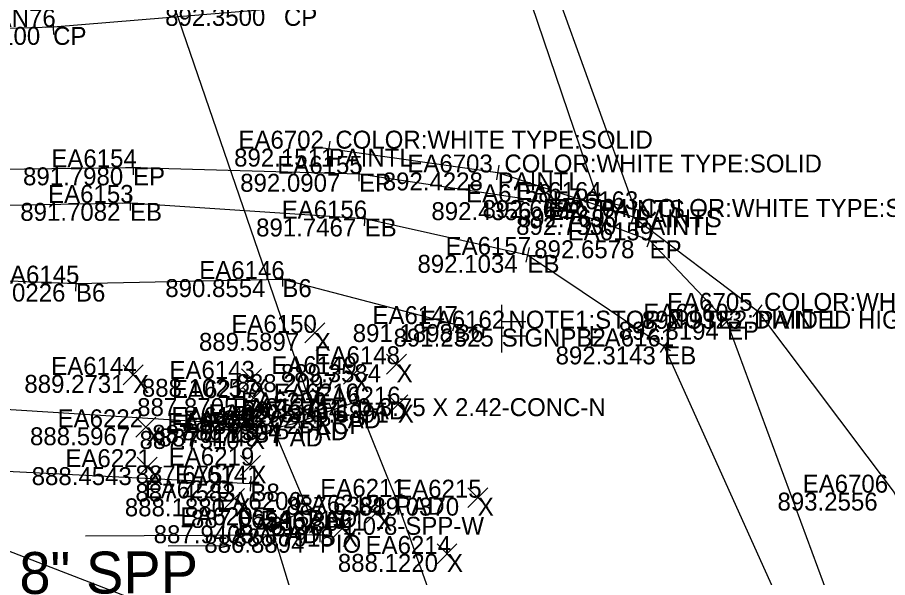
# Model space of a CAD drawing. Extents: x 179044 to 189691, y 286531 to 301257.
# Drawn here: x 180169.6 to 180227.8, y 300553.8 to 300591.3 of the extents above; entities that cross this region are included whole.
import ezdxf

# ---------------------------------------------------------------- set-up
doc = ezdxf.new("R2010")
doc.units = 0
for name, color, linetype in [('DR_X_Elev_Flow', 7, 'Continuous'), ('DR_X_Storm_Sewer', 7, 'Continuous'), ('DR_X_Text', 7, 'Continuous'), ('PM_X_Channelizing_Line', 7, 'Continuous'), ('PM_X_Stop_Line', 7, 'Continuous'), ('PV_X_COP', 7, 'Continuous'), ('PV_X_EOP', 7, 'Continuous'), ('PV_X_Shoulder_Aggregate', 7, 'Continuous'), ('RD_X_Concrete_Pad', 7, 'Continuous'), ('SN_X_Public', 7, 'Continuous'), ('SV_X_Break_Lines', 7, 'Continuous'), ('SV_X_Random_Point', 7, 'Continuous'), ('SV_X_Shot_Marker', 7, 'Continuous'), ('SV_X_Text_Comment', 7, 'Continuous'), ('SV_X_Text_Description', 7, 'Continuous'), ('SV_X_Text_Elevation', 7, 'Continuous'), ('SV_X_Text_Name', 7, 'Continuous')]:
    doc.layers.add(name, color=color, linetype=linetype)

msp = doc.modelspace()

# ---------------------------------------------------------------- linework, layer by layer
at = {"layer": 'DR_X_Elev_Flow'}
for p, q in [((180189.362, 300556.677), (180190.362, 300556.677)), ((180189.837, 300556.677), (180189.887, 300556.677)), ((180189.862, 300557.177), (180189.862, 300556.177)), ((180189.862, 300556.701), (180189.862, 300556.651)), ((180189.862, 300556.677), (180189.862, 300556.677)), ((180189.862, 300556.677), (180189.862, 300556.677))]:
    msp.add_line(p, q, dxfattribs=at)
at = {"layer": 'DR_X_Storm_Sewer'}
for p, q in [((180165.628, 300634.286), (180189.523, 300564.613)), ((180189.862, 300556.677), (180174.195, 300556.579))]:
    msp.add_line(p, q, dxfattribs=at)
at = {"layer": 'DR_X_Text'}
msp.add_line((180179.718, 300555.93), (180183.911, 300555.956), dxfattribs=at)
msp.add_lwpolyline([(180183.212, 300555.802), (180183.21, 300556.102), (180183.911, 300555.956)], close=True, dxfattribs=at)
at = {"layer": 'PM_X_Channelizing_Line'}
msp.add_lwpolyline([(180190.445, 300582.496), (180201.741, 300580.903), (180210.797, 300577.931), (180219.101, 300571.651), (180228.235, 300559.496), (180237.94, 300538.543), (180264.924, 300467.918), (180293.4, 300391.707), (180324.643, 300308.043), (180350.475, 300238.896)], dxfattribs=at)
at = {"layer": 'PM_X_Stop_Line'}
msp.add_lwpolyline([(180210.916, 300578.442), (180208.457, 300579.058), (180203.618, 300593.325), (180205.342, 300593.885)], close=True, dxfattribs=at)
at = {"layer": 'PV_X_COP'}
msp.add_lwpolyline([(179370.611, 300584.893), (179476.831, 300585.936), (179562.951, 300586.92), (179659.852, 300587.603), (179771.173, 300587.773), (179881.154, 300588.595), (179985.728, 300588.166), (180079.826, 300588.612), (180147.691, 300589.874), (180172.034, 300590.636), (180187.456, 300591.905), (180203.618, 300593.325)], dxfattribs=at)
at = {"layer": 'PV_X_EOP'}
msp.add_lwpolyline([(179371.146, 300578.051), (179477.168, 300579.528), (179563.012, 300579.455), (179660.626, 300579.907), (179772.349, 300580.843), (179883.302, 300581.216), (179986.953, 300581.659), (180080.461, 300581.624), (180131.142, 300581.875), (180152.421, 300580.897), (180177.372, 300581.245), (180192.481, 300580.813), (180205.116, 300578.916), (180211.895, 300576.366), (180217.061, 300570.924), (180226.256, 300546.032), (180252.64, 300475.662), (180284.891, 300388.784), (180312.046, 300315.753), (180341.998, 300235.308)], dxfattribs=at)
at = {"layer": 'PV_X_Shoulder_Aggregate'}
msp.add_lwpolyline([(179563.451, 300578.229), (179660.977, 300578.016), (179772.748, 300578.901), (179883.7, 300579.446), (179986.895, 300579.719), (180080.262, 300579.655), (180131.517, 300579.632), (180152.892, 300578.404), (180177.169, 300578.87), (180192.854, 300577.824), (180203.732, 300575.396), (180212.869, 300569.272), (180224.05, 300544.426), (180250.422, 300474.503), (180282.665, 300386.992), (180309.922, 300313.986), (180339.844, 300234.334)], dxfattribs=at)
at = {"layer": 'RD_X_Concrete_Pad'}
msp.add_lwpolyline([(180197.385, 300552.231), (180195.522, 300551.693), (180192.478, 300550.79), (180189.063, 300549.217), (180186.577, 300557.315), (180189.052, 300558.338), (180186.77, 300563.783), (180188.444, 300564.199), (180190.647, 300565), (180192.332, 300565.592), (180194.898, 300559.216)], close=True, dxfattribs=at)
at = {"layer": 'SN_X_Public'}
for p, q in [((180202.013, 300568.861), (180202.013, 300572.061)), ((180202.013, 300570.941), (180203.613, 300570.941)), ((180202.013, 300570.461), (180202.013, 300570.461)), ((180202.013, 300569.981), (180203.613, 300569.981))]:
    msp.add_line(p, q, dxfattribs=at)
at = {"layer": 'SV_X_Break_Lines'}
for points in [[(179565.115, 300573.15), (179662.025, 300574.398), (179773.068, 300575.457), (179882.867, 300576.482), (179986.954, 300576.827), (180079.906, 300577.073), (180132.276, 300575.162), (180173.558, 300573.472), (180187.352, 300573.774), (180198.853, 300570.766)], [(179565.766, 300571.109), (179663.199, 300570.888), (179773.087, 300572.831), (179882.326, 300573.106), (179987.447, 300574.391), (180079.006, 300574.101), (180132.144, 300569.99), (180164.614, 300565.351), (180185.409, 300564.026)], [(179565.763, 300567.872), (179663.335, 300568.017), (179772.883, 300569.466), (179881.609, 300569.697), (179987.857, 300571.139), (180079.155, 300570.638), (180132.418, 300565.887), (180165.824, 300561.088), (180185.221, 300560.101)], [(180320.902, 300212.184), (180282.069, 300307.438), (180254.033, 300376.286), (180214.216, 300457.225), (180192.833, 300518.475), (180187.002, 300524.649), (180178.544, 300551.918), (180167.492, 300556.189), (180133.433, 300560.27), (180078.668, 300564.705), (179988.563, 300564.714), (179881.16, 300565.14), (179774.574, 300564.41), (179665.201, 300563.792), (179565.532, 300563.693)]]:
    msp.add_lwpolyline(points, dxfattribs=at)
at = {"layer": 'SV_X_Random_Point'}
for p, q in [((180188.853, 300569.51), (180190.186, 300570.845)), ((180188.853, 300570.845), (180190.186, 300569.51)), ((180194.321, 300567.415), (180195.654, 300568.75)), ((180194.321, 300568.75), (180195.654, 300567.415)), ((180176.708, 300566.7), (180178.041, 300568.035)), ((180176.708, 300568.035), (180178.041, 300566.7)), ((180184.618, 300566.437), (180185.951, 300567.772)), ((180184.618, 300567.772), (180185.951, 300566.437)), ((180191.437, 300566.751), (180192.771, 300568.086)), ((180191.437, 300568.086), (180192.771, 300566.751)), ((180184.761, 300565.149), (180186.094, 300566.484)), ((180184.761, 300566.484), (180186.094, 300565.149)), ((180194.402, 300564.712), (180195.735, 300566.047)), ((180194.402, 300566.047), (180195.735, 300564.712)), ((180177.56, 300563.198), (180178.893, 300564.533)), ((180177.56, 300564.533), (180178.893, 300563.198)), ((180184.453, 300562.951), (180185.786, 300564.286)), ((180184.453, 300564.286), (180185.786, 300562.951)), ((180177.652, 300560.535), (180178.986, 300561.869)), ((180177.652, 300561.869), (180178.986, 300560.535)), ((180184.558, 300560.643), (180185.891, 300561.978)), ((180184.558, 300561.978), (180185.891, 300560.643)), ((180183.49, 300558.445), (180184.824, 300559.78)), ((180183.49, 300559.78), (180184.824, 300558.445)), ((180199.742, 300558.493), (180201.076, 300559.828)), ((180199.742, 300559.828), (180201.076, 300558.493)), ((180192.963, 300557.483), (180194.296, 300558.818)), ((180192.963, 300558.818), (180194.296, 300557.483)), ((180190.68, 300556.421), (180192.013, 300557.757)), ((180190.68, 300557.757), (180192.013, 300556.421)), ((180197.688, 300554.733), (180199.021, 300556.068)), ((180197.688, 300556.068), (180199.021, 300554.733))]:
    msp.add_line(p, q, dxfattribs=at)
at = {"layer": 'SV_X_Shot_Marker'}
for p, q in [((180172.019, 300591.136), (180172.05, 300590.136)), ((180171.535, 300590.621), (180172.534, 300590.652)), ((180172.034, 300590.636), (180172.034, 300590.636)), ((180190.515, 300582.991), (180190.375, 300582)), ((180189.95, 300582.565), (180190.94, 300582.426)), ((180190.445, 300582.496), (180190.445, 300582.496)), ((180177.365, 300581.745), (180177.379, 300580.745)), ((180176.872, 300581.238), (180177.872, 300581.252)), ((180177.372, 300581.245), (180177.372, 300581.245)), ((180192.495, 300581.313), (180192.467, 300580.313)), ((180201.811, 300581.398), (180201.671, 300580.408)), ((180191.981, 300580.827), (180192.981, 300580.799)), ((180192.481, 300580.813), (180192.481, 300580.813)), ((180201.246, 300580.973), (180202.236, 300580.833)), ((180201.741, 300580.903), (180201.741, 300580.903)), ((180177.159, 300579.37), (180177.178, 300578.37)), ((180205.19, 300579.41), (180205.041, 300578.421)), ((180208.336, 300578.573), (180208.578, 300579.543)), ((180176.669, 300578.861), (180177.669, 300578.88)), ((180177.169, 300578.87), (180177.169, 300578.87)), ((180204.621, 300578.99), (180205.61, 300578.841)), ((180205.116, 300578.916), (180205.116, 300578.916)), ((180208.942, 300578.936), (180207.972, 300579.179)), ((180208.457, 300579.058), (180208.457, 300579.058)), ((180210.795, 300577.957), (180211.037, 300578.927)), ((180192.887, 300578.323), (180192.821, 300577.325)), ((180211.401, 300578.321), (180210.431, 300578.564)), ((180210.953, 300578.406), (180210.642, 300577.456)), ((180210.916, 300578.442), (180210.916, 300578.442)), ((180192.355, 300577.857), (180193.353, 300577.791)), ((180192.854, 300577.824), (180192.854, 300577.824)), ((180210.322, 300578.087), (180211.273, 300577.776)), ((180210.797, 300577.931), (180210.797, 300577.931)), ((180211.428, 300576.542), (180212.363, 300576.19)), ((180212.072, 300576.834), (180211.719, 300575.898)), ((180203.841, 300575.884), (180203.623, 300574.908)), ((180211.895, 300576.366), (180211.895, 300576.366)), ((180203.244, 300575.505), (180204.22, 300575.287)), ((180203.732, 300575.396), (180203.732, 300575.396)), ((180187.341, 300574.274), (180187.363, 300573.274)), ((180173.059, 300573.492), (180174.058, 300573.451)), ((180173.579, 300573.971), (180173.538, 300572.972)), ((180186.852, 300573.763), (180187.852, 300573.785)), ((180187.352, 300573.774), (180187.352, 300573.774)), ((180173.558, 300573.472), (180173.558, 300573.472)), ((180218.702, 300571.952), (180219.5, 300571.349)), ((180219.403, 300572.05), (180218.799, 300571.252)), ((180198.98, 300571.25), (180198.727, 300570.282)), ((180217.423, 300571.269), (180216.698, 300570.58)), ((180216.716, 300571.287), (180217.405, 300570.562)), ((180219.101, 300571.651), (180219.101, 300571.651)), ((180198.37, 300570.893), (180199.337, 300570.64)), ((180198.853, 300570.766), (180198.853, 300570.766)), ((180217.061, 300570.924), (180217.061, 300570.924)), ((180212.454, 300569.55), (180213.284, 300568.993)), ((180213.147, 300569.687), (180212.591, 300568.856)), ((180212.869, 300569.272), (180212.869, 300569.272)), ((180192.166, 300566.064), (180192.498, 300565.12)), ((180190.476, 300565.47), (180190.818, 300564.53)), ((180191.86, 300565.426), (180192.804, 300565.758)), ((180192.332, 300565.592), (180192.332, 300565.592)), ((180189.523, 300565.113), (180189.523, 300564.113)), ((180190.177, 300564.829), (180191.117, 300565.171)), ((180190.647, 300565), (180190.647, 300565)), ((180185.441, 300564.525), (180185.377, 300563.527)), ((180186.963, 300563.322), (180186.576, 300564.245)), ((180187.959, 300564.079), (180188.93, 300564.32)), ((180188.324, 300564.685), (180188.565, 300563.714)), ((180188.444, 300564.199), (180188.444, 300564.199)), ((180189.023, 300564.613), (180190.023, 300564.613)), ((180189.498, 300564.613), (180189.548, 300564.613)), ((180189.523, 300564.638), (180189.523, 300564.588)), ((180189.523, 300564.613), (180189.523, 300564.613)), ((180189.523, 300564.613), (180189.523, 300564.613)), ((180184.91, 300564.058), (180185.908, 300563.995)), ((180185.409, 300564.026), (180185.409, 300564.026)), ((180186.309, 300563.59), (180187.231, 300563.977)), ((180186.77, 300563.783), (180186.77, 300563.783)), ((180184.722, 300560.127), (180185.721, 300560.076)), ((180185.247, 300560.601), (180185.196, 300559.602)), ((180185.221, 300560.101), (180185.221, 300560.101)), ((180194.712, 300559.68), (180195.085, 300558.752)), ((180195.362, 300559.402), (180194.435, 300559.029)), ((180194.898, 300559.216), (180194.898, 300559.216)), ((180188.59, 300558.147), (180189.514, 300558.529)), ((180188.861, 300558.8), (180189.243, 300557.876)), ((180186.724, 300556.837), (180186.43, 300557.793)), ((180189.052, 300558.338), (180189.052, 300558.338)), ((180186.099, 300557.168), (180187.055, 300557.462)), ((180186.577, 300557.315), (180186.577, 300557.315))]:
    msp.add_line(p, q, dxfattribs=at)

# ---------------------------------------------------------------- texts
at = {"layer": 'DR_X_Text'}
msp.add_text('8" SPP', height=2.8, rotation=0.35657, dxfattribs=at).set_placement((180169.784, 300552.718))
at = {"layer": 'SV_X_Text_Comment'}
for s, height, p in [('CP', 1.2, (180187.456, 300590.705)), ('CP', 1.2, (180172.034, 300589.436)), ('PAINTL', 1.2, (180190.445, 300581.296)), ('EP', 1.2, (180177.372, 300580.045)), ('EP', 1.2, (180192.481, 300579.613)), ('PAINTL', 1.2, (180201.741, 300579.703)), ('EB', 1.2, (180177.169, 300577.67)), ('EP', 1.2, (180205.116, 300577.716)), ('PAINTS', 1.2, (180208.457, 300577.858)), ('PAINTS', 1.2, (180210.916, 300577.242)), ('EB', 1.2, (180192.854, 300576.624)), ('PAINTL', 1.2, (180210.797, 300576.731)), ('EP', 1.2, (180211.895, 300575.166)), ('EB', 1.2, (180203.732, 300574.196)), ('B6', 1.2, (180173.558, 300572.272)), ('B6', 1.2, (180187.352, 300572.574)), ('PAINTL', 1.2, (180219.101, 300570.451)), ('B6', 1.2, (180198.853, 300569.566)), ('EP', 1.2, (180217.061, 300569.724)), ('X', 1.2, (180189.519, 300568.978)), ('SIGNPB2', 1.2, (180202.013, 300569.261)), ('EB', 1.2, (180212.869, 300568.072)), ('X', 1.2, (180194.987, 300566.882)), ('X', 1.2, (180177.374, 300566.168)), ('X', 1.2, (180185.285, 300565.905)), ('X', 1.2, (180192.104, 300566.219)), ('X', 1.2, (180185.427, 300564.617)), ('PAD', 1.2, (180192.332, 300564.392)), ('X', 1.2, (180195.068, 300564.18)), ('PAD', 1.2, (180190.647, 300563.8)), ('PAD', 1.2, (180188.444, 300562.999)), ('P1=0-3.75 X 2.42-CONC-N', 0.06, (180189.523, 300564.553)), ('RCP', 1.2, (180189.523, 300563.413)), ('X', 1.2, (180178.226, 300562.665)), ('X', 1.2, (180185.12, 300562.419)), ('B7', 1.2, (180185.409, 300562.826)), ('PAD', 1.2, (180186.77, 300562.583)), ('X', 1.2, (180185.224, 300560.111)), ('X', 1.2, (180178.319, 300560.002)), ('B8', 1.2, (180185.221, 300558.901)), ('X', 1.2, (180184.157, 300557.913)), ('PAD', 1.2, (180194.898, 300558.016)), ('X', 1.2, (180200.409, 300557.96)), ('PAD', 1.2, (180189.052, 300557.138)), ('X', 1.2, (180193.63, 300556.951)), ('PAD', 1.2, (180186.577, 300556.115)), ('P1=0-8-SPP-W', 0.06, (180189.862, 300556.617)), ('PIO', 1.2, (180189.862, 300555.476)), ('X', 1.2, (180191.347, 300555.889)), ('X', 1.2, (180198.354, 300554.2))]:
    msp.add_text(s, height=height, dxfattribs=at).set_placement(p)
at = {"layer": 'SV_X_Text_Description'}
for s, height, p in [(' COLOR:WHITE TYPE:SOLID', 1.2, (180190.445, 300582.496)), (' COLOR:WHITE TYPE:SOLID', 1.2, (180201.741, 300580.903)), (' COLOR:WHITE TYPE:SOLID', 1.2, (180210.797, 300577.931)), (' COLOR:WHITE TYPE:SOLID', 1.2, (180219.101, 300571.651)), (' NOTE1:STOP NOTE2:DIVIDED HIGHWAY', 1.2, (180202.013, 300570.461)), (' P1:0-3.75 X 2.42-CONC-N', 1.2, (180189.523, 300564.613)), (' P1:0-8-SPP-W', 1.2, (180189.862, 300556.677)), ('P1= 0-8-SPP-W', 0.06, (180189.862, 300556.677))]:
    msp.add_text(s, height=height, dxfattribs=at).set_placement(p)
at = {"layer": 'SV_X_Text_Elevation'}
for s, height, p in [('892.3500', 1.2, (180179.52, 300590.705)), ('892.0100', 1.2, (180164.476, 300589.436)), ('892.1511', 1.2, (180184.128, 300581.296)), ('891.7980', 1.2, (180170.022, 300580.045)), ('892.0907', 1.2, (180184.535, 300579.613)), ('892.4228', 1.2, (180194.06, 300579.703)), ('891.7082', 1.2, (180169.838, 300577.67)), ('892.4356', 1.2, (180197.311, 300577.716)), ('892.6682', 1.2, (180200.728, 300577.858)), ('892.7690', 1.2, (180203.093, 300577.242)), ('891.7467', 1.2, (180185.598, 300576.624)), ('892.7330', 1.2, (180202.974, 300576.731)), ('892.6578', 1.2, (180204.186, 300575.166)), ('892.1034', 1.2, (180196.381, 300574.196)), ('891.0226', 1.2, (180166.161, 300572.272)), ('890.8554', 1.2, (180179.529, 300572.574)), ('892.9323', 1.2, (180211.382, 300570.451)), ('891.1898', 1.2, (180192.052, 300569.566)), ('892.8194', 1.2, (180209.824, 300569.724)), ('889.5897', 1.2, (180181.781, 300568.978)), ('891.2325', 1.2, (180194.786, 300569.261)), ('892.3143', 1.2, (180205.613, 300568.072)), ('889.3584', 1.2, (180187.259, 300566.882)), ('889.2731', 1.2, (180170.111, 300566.168)), ('888.1025', 1.2, (180177.963, 300565.905)), ('888.2097', 1.2, (180184.29, 300566.219)), ('887.8705', 1.2, (180177.651, 300564.617)), ('887.5764', 1.2, (180184.66, 300564.392)), ('888.6891', 1.2, (180187.768, 300564.18)), ('886.6219', 1.2, (180183.391, 300563.8)), ('886.7304', 1.2, (180180.621, 300562.999)), ('886.5872', 1.2, (180181.832, 300563.413)), ('886.59', 0.06, (180189.24, 300564.553)), ('888.5967', 1.2, (180170.488, 300562.665)), ('887.7310', 1.2, (180177.807, 300562.419)), ('887.6113', 1.2, (180178.655, 300562.826)), ('887.4749', 1.2, (180179.079, 300562.583)), ('887.6757', 1.2, (180177.543, 300560.111)), ('888.4543', 1.2, (180170.6, 300560.002)), ('887.4583', 1.2, (180177.531, 300558.901)), ('888.1880', 1.2, (180176.826, 300557.913)), ('887.6381', 1.2, (180187.617, 300558.016)), ('889.0370', 1.2, (180192.473, 300557.96)), ('893.2556', 1.2, (180220.44, 300558.296)), ('887.0654', 1.2, (180181.248, 300557.138)), ('886.8061', 1.2, (180186.216, 300556.951)), ('887.9403', 1.2, (180178.754, 300556.115)), ('886.8894', 1.2, (180182.134, 300555.476)), ('886.7918', 1.2, (180184.091, 300555.889)), ('886.89', 0.06, (180189.58, 300556.617)), ('888.1220', 1.2, (180191.061, 300554.2))]:
    msp.add_text(s, height=height, dxfattribs=at).set_placement(p)
at = {"layer": 'SV_X_Text_Name'}
for s, height, p in [('MAN76', 1.2, (180166.857, 300590.636)), ('EA6702', 1.2, (180184.417, 300582.496)), ('EA6154', 1.2, (180171.912, 300581.245)), ('EA6155', 1.2, (180187.011, 300580.813)), ('EA6703', 1.2, (180195.704, 300580.903)), ('EA6153', 1.2, (180171.699, 300578.87)), ('EA6158', 1.2, (180199.636, 300578.916)), ('EA6164', 1.2, (180202.978, 300579.058)), ('EA6163', 1.2, (180205.427, 300578.442)), ('EA6156', 1.2, (180187.309, 300577.824)), ('EA6704', 1.2, (180204.77, 300577.931)), ('EA6159', 1.2, (180206.416, 300576.366)), ('EA6157', 1.2, (180198.262, 300575.396)), ('EA6145', 1.2, (180168.079, 300573.472)), ('EA6146', 1.2, (180181.797, 300573.774)), ('EA6705', 1.2, (180213.064, 300571.651)), ('EA6147', 1.2, (180193.374, 300570.766)), ('EA6160', 1.2, (180211.468, 300570.924)), ('EA6150', 1.2, (180183.946, 300570.178)), ('EA6162', 1.2, (180196.534, 300570.461)), ('EA6161', 1.2, (180207.818, 300569.272)), ('EA6148', 1.2, (180189.499, 300568.082)), ('EA6144', 1.2, (180171.904, 300567.368)), ('EA6143', 1.2, (180179.805, 300567.105)), ('EA6149', 1.2, (180186.615, 300567.419)), ('EA6217', 1.2, (180179.976, 300565.817)), ('EA6210', 1.2, (180186.777, 300565.592)), ('EA6216', 1.2, (180189.542, 300565.38)), ('EA6209', 1.2, (180184.6, 300565)), ('EA6208', 1.2, (180182.398, 300564.199)), ('EA6137', 1.2, (180184.034, 300564.613)), ('EA6222', 1.2, (180172.331, 300563.865)), ('EA6218', 1.2, (180179.659, 300563.619)), ('EA6142', 1.2, (180179.939, 300564.026)), ('EA6207', 1.2, (180180.732, 300563.783)), ('EA6137', 0.06, (180189.248, 300564.613)), ('EA6219', 1.2, (180179.764, 300561.311)), ('EA6221', 1.2, (180172.852, 300561.202)), ('EA6141', 1.2, (180180.18, 300560.101)), ('EA6706', 1.2, (180222.122, 300559.496)), ('EA6220', 1.2, (180178.148, 300559.113)), ('EA6211', 1.2, (180189.885, 300559.216)), ('EA6215', 1.2, (180194.958, 300559.16)), ('EA6206', 1.2, (180182.939, 300558.338)), ('EA6212', 1.2, (180188.188, 300558.151)), ('EA6205', 1.2, (180180.54, 300557.315)), ('EA6138', 1.2, (180184.364, 300556.677)), ('EA6213', 1.2, (180185.896, 300557.089)), ('EA6138', 0.06, (180189.587, 300556.677)), ('EA6214', 1.2, (180192.913, 300555.4))]:
    msp.add_text(s, height=height, dxfattribs=at).set_placement(p)

doc.saveas('drawing.dxf')
